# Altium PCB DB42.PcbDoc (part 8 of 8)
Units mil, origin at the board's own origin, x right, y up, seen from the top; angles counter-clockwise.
Board outline 3236.22 x 4456.69 mil, 8 copper layers (Top Layer, MidLayer1, MidLayer2, GND-Layer5, MidLayer3, VCC, MidLayer4, Bottom Layer), stack 62.194 mil thick; 214 components, 470 nets, 1802 pads, 1663 vias.
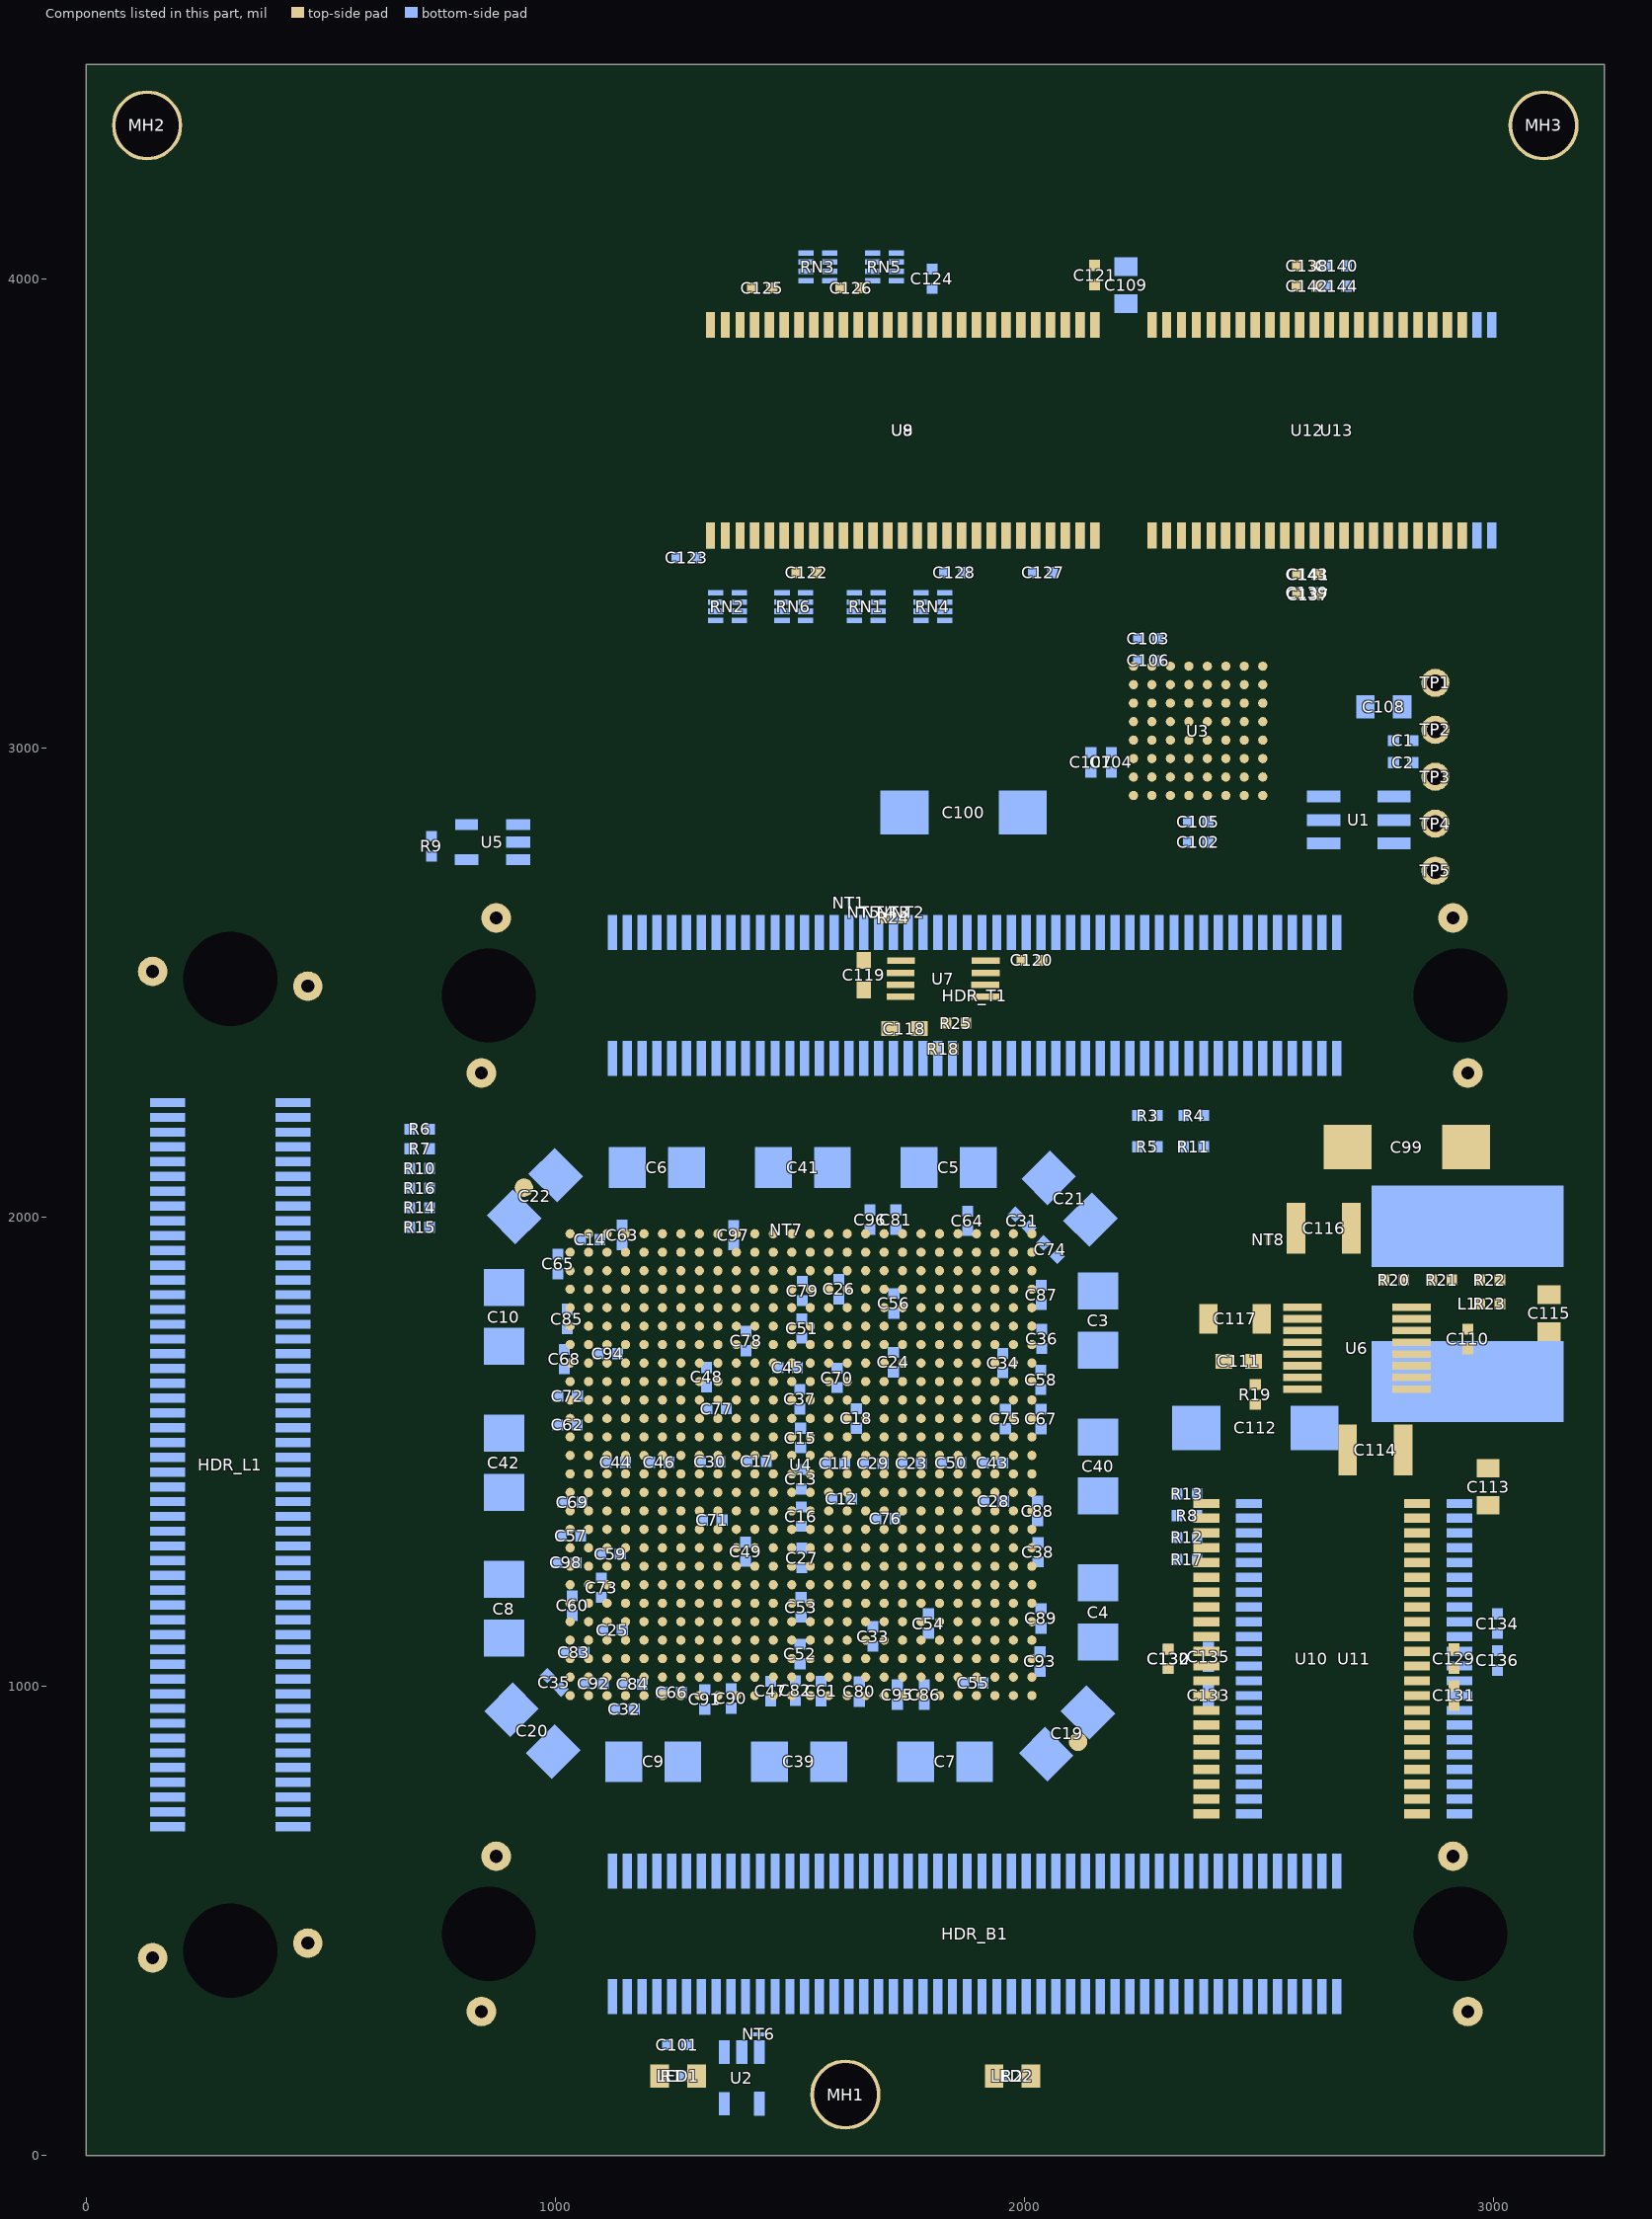
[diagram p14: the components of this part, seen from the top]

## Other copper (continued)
Bottom Layer:
  rectangle net 1V2: 2641.13,1901.74 2787.4,2043.82
  rectangle net LX: 2637.8,1618.11 2799.21,1728.35
  rectangle net 5V0: 2629.92,2248.03 2740.16,2346.46
  rectangle net 5V0: 2645.67,2248.03 2740.16,2346.46
  rectangle net 3V3: 2562.99,2570.86 2610.24,2704.72
  rectangle net 3V3: 2562.99,570.86 2610.24,704.72
  rectangle net GND: 2645.67,2598.43 2740.16,2696.85
  rectangle net 5V0: 2645.67,251.97 2740.16,346.46
  rectangle net GND: 2645.67,598.43 2740.16,696.85
GND-Layer5 (plane layer: these items are gaps in the copper):
  rectangle: 2645.67,2251.97 2740.16,2283.46
  rectangle: 2708.66,2283.47 2740.16,2346.46
  rectangle: 2570.87,2661.42 2602.36,2724.41
  rectangle: 2661.42,1641.73 2720.47,1696.85
  rectangle: 2645.67,251.97 2708.66,283.46
  rectangle: 2708.66,314.96 2740.16,346.46
  rectangle: 2570.87,661.42 2602.36,724.41
  text "GND" at 1645.67,437.01 h60
VCC (plane layer: these items are gaps in the copper):
  rectangle: 3102.36,4334.65 3228.35,4444.88
  rectangle: 23.62,4330.71 129.92,4440.94
  lines w19.68: 2624.02,0 2624.02,356.3 2787.4,519.68 2787.4,637.8 2838.58,688.98 2952.76,688.98 3055.12,791.34 3055.12,1244.09 3055.12,1287.4 3055.12,1389.76 3009.88,1435 2740,1435 2735,1440 2735,1587.6 2716.3,1606.3 2614.17,1606.3 2582.68,1574.8 2452.76,1574.8 2437.01,1590.55 2437.01,2015.75 2624.02,2202.76 2624.02,2383.86 2629.92,2389.76 2795.28,2389.76 2917.32,2267.72 3068.72,2267.72 3116,2315 3116,3975 3046,4045 2728,4045 2711.76,4061.24 2711.76,4456.69
  lines w30: 25.58,627.79 25.58,36.41 36.41,25.58 3205.87,25.58 3210.79,30.5 3210.79,4423.08 3201.94,4431.94 3124.2,4431.94 3123.22,4432.92 38.38,4432.92 27.55,4422.1 27.55,628.78
  text "5V0" at 2791.34,1826.77 h60
  text "3V3" at 1657.48,437.01 h60

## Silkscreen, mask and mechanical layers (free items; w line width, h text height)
Top Overlay:
  rectangle: 998.77,581.74 1627.79,617.74
  rectangle: 998.77,318.48 1627.79,354.48
  rectangle: 2710.5,318.48 2788.79,617.48
  region: 1073.79,617.74 998.77,617.74 998.77,318.48 1073.79,318.48
  region: 1689.96,4181.1 1689.96,4456.69 1670.28,4456.69 1670.28,4181.1
  region: 1598.43,4181.1 1598.43,4456.69 1593.51,4456.69 1593.51,4181.1
  region: 1618.11,4181.1 1618.11,4456.69 1610.24,4456.69 1610.24,4181.1
  region: 1640.75,4181.1 1640.75,4456.69 1628.94,4456.69 1628.94,4181.1
  region: 1664.37,4181.1 1664.37,4456.69 1649.61,4456.69 1649.61,4181.1
  region: 1579.72,4181.1 1579.72,4456.69 1576.77,4456.69 1576.77,4181.1
  rectangle: 1301.18,3503.94 2179.13,3596.46
  rectangle: 2238.19,3502.95 2966.89,3595.47
  region: 2787.4,695.23 2787.4,1424.21 2694.88,1424.21 2694.88,695.23
  rectangle: 1775.59,2456.69 1803,2559.05
  rectangle: 1337.26,129.92 1351.38,208.66
  rectangle: 2049.67,129.92 2063.98,208.66
  rectangle: 2736.22,1620.75 2768.58,1820.75
  region: 1840.85,253.71 1833.78,260.78 1756,183 1763.07,175.93
  rectangle: 1756,183 1766,218
  region: 1772.38,166.61 1779.46,159.54 1857.24,237.33 1850.17,244.4
  region: 1814.46,159.54 1814.46,169.54 1779.46,169.54 1779.46,159.54
  region: 3099.71,4136.09 3089.71,4136.09 3089.71,4026.09 3099.71,4026.09
  region: 3064.97,4111.34 3072.04,4104.27 3096.79,4129.02 3089.71,4136.09
  rectangle: 3112.89,4026.09 3122.89,4136.09
  region: 3122.89,4136.09 3115.82,4129.02 3140.56,4104.27 3147.64,4111.34
  region: 123.34,4136.09 113.34,4136.09 113.34,4026.09 123.34,4026.09
  region: 88.59,4111.34 95.66,4104.27 120.41,4129.02 113.34,4136.09
  rectangle: 136.51,4026.09 146.51,4136.09
  region: 146.51,4136.09 139.44,4129.02 164.19,4104.27 171.26,4111.34
  lines w3: 1118.09,192.91 1133.09,202.91 1123.09,202.91 1143.09,217.91 ; 1133.09,207.91 1143.09,217.91 ; 1133.09,212.91 1143.09,217.91 ; 2137.52,187.01 2152.52,197.01 2142.52,197.01 2162.52,212.01 ; 2152.52,202.01 2162.52,212.01 ; 2152.52,207.01 2162.52,212.01
  lines w5: 971.79,2024.27 992.13,2003.94 ; 1078.13,171.78 1103.06,171.78 ; 1103.06,173.36 1126.68,173.36 ; 1104.64,163.12 1126.68,172.05 ; 1104.64,180.97 1126.68,172.05 ; 1105.03,168.63 1126.68,172.96 ; 1105.03,175.46 1126.68,171.13 ; 1126.68,156.3 1126.68,187.79 ; 1126.68,171.78 1150.04,171.78 ; 1329.1,3386.03 1329.1,3414.79 ; 1687.62,2591.03 1707.96,2570.7 ; 2097.56,165.88 2122.48,165.88 ; 2122.48,167.45 2146.1,167.45 ; 2124.06,157.21 2146.1,166.14 ; 2124.06,175.07 2146.1,166.14 ; 2124.45,162.73 2146.1,167.06 ; 2124.45,169.56 2146.1,165.23 ; 2146.1,150.39 2146.1,181.89 ; 2146.1,165.88 2169.46,165.88 ; 2271.78,3384.98 2271.78,3413.74 ; 2646.32,3273.29 2625.98,3252.95 ; 2907.18,728.42 2878.41,728.42 ; 2908.93,1634.16 2880.16,1634.16 ; 3031.5,1822.83 3073.01,1882.13 ; 992.13,2003.94 964.13,2016.94 971.68,2024.38 979.13,2031.94 992.13,2003.94 ; 1126.68,172.05 1103.06,187.79 1103.06,156.3 1126.68,172.05 ; 1329.1,3414.79 1318.5,3385.8 1329.1,3385.88 1339.71,3385.8 1329.1,3414.79 ; 1707.96,2570.7 1694.96,2598.69 1687.52,2591.14 1679.96,2583.69 1707.96,2570.7 ; 2146.1,166.14 2122.48,150.39 2122.48,181.89 2146.1,166.14 ; 2271.78,3413.74 2282.39,3384.75 2271.78,3384.83 2261.17,3384.75 2271.78,3413.74 ; 2625.98,3252.95 2638.98,3280.95 2646.43,3273.4 2653.98,3265.95 2625.98,3252.95 ; 2878.41,728.42 2907.4,717.82 2907.33,728.42 2907.4,739.03 2878.41,728.42 ; 2880.16,1634.16 2909.15,1623.56 2909.08,1634.16 2909.15,1644.77 2880.16,1634.16
  lines w7: 971.13,2018.93 978.13,2011.94 ; 977.13,2024.94 984.13,2017.94 ; 1324.86,3389.33 1324.86,3399.23 ; 1333.35,3389.33 1333.35,3399.23 ; 1686.96,2585.69 1693.96,2578.69 ; 1692.96,2591.69 1699.96,2584.69 ; 2267.54,3388.29 2267.54,3398.18 ; 2276.02,3388.29 2276.02,3398.18 ; 2633.98,3266.95 2640.98,3273.95 ; 2639.98,3260.95 2646.98,3267.95 ; 2893.97,724.18 2903.87,724.18 ; 2893.97,732.67 2903.87,732.67 ; 2895.72,1629.92 2905.62,1629.92 ; 2895.72,1638.41 2905.62,1638.41
  lines w7.87: 1301.18,3722.33 ccw(c1301.18,3752.07) 1301.18,3781.82 ; 2179.13,3722.33 cw(c2179.13,3752.07) 2179.13,3781.82 ; 1708.66,4185.04 1708.66,4452.76 2972.66,4452.76 2972.66,4185.04 1708.66,4185.04
  text "Xilinx®  Spartan™3A-DSP" at 1708.66,4311.02 h98.43
  text "XC3SD1800A-4FGG676C" at 1708.66,4185.04 h98.43
  text "SRAM-256Kx16" at 2352.07,3683.79 h50
  text "DRAM-16Mx16" at 1482.53,3682.61 h50
  text "FLASH" at 2491.1,2767.2 h34
  text "MAX" at 1831.9,2475.9 h22 r90
  text "8860" at 1865.1,2465.2 h25 r90
  text "1831" at 2721.4,1671.7 h40 r90
  text "SRAM-256Kx16" at 2605.68,808.76 h50 r90
  text "DB42.02" at 1027.8,488.46 h98.42
  text "XC3SD1800A-4FGG676C" at 1027.8,430.47 h60
  text "Xilinx Daughter Board" at 1028.31,354.49 h60
  text "DB42.02" at 1625.79,318.46 h60
  text "PROGRAM" at 1145,60 h55.12
  text "POWER" at 1895,60 h55.12
Bottom Overlay:
  drawing of 1137 lines, arcs and shapes, not listed
  text "Xilinx®  Spartan™3A-DSP" at 2968.73,4318.9 h98.43
  text "XC3SD1800A-4FGG676C" at 2968.73,4185.04 h98.43
  text "MANUFACTURE" at 1006.78,3830.86 h40
  text "DATE" at 1007.88,3764.06 h40
  text "SRAM-256Kx16" at 2939.9,3684 h50
  text "DRAM-16Mx16" at 1997.78,3682.61 h50
  text ".Application_BuildNumber" at 627.63,3398.29 h60
  text "BUILD No:" at 901.4,3398.07 h34
  text "SVN 9250" at 627.63,3338.95 h60
  text "REVISION No:" at 976.18,3338.74 h34
  text "PCB MANUFACTURER:" at 1185.04,3279.53 h34
  text "COMPLIANCE:" at 1182.36,3081.45 h45
  text "CLASS 2" at 432.36,2991.45 h40
  text "IPC-A-600H" at 1092.36,2991.45 h40
  text "CLASS 2" at 432.36,2911.45 h40
  text "TYPE 3" at 682.36,2911.45 h40
  text "IPC-6012D" at 1092.36,2911.45 h40
  text "DS2406" at 2711.2,2774.8 h28 r270
  text "1" at 116.93,2272.44 h39.37
  text "1" at 1085.43,2256.69 h39.37
  text "SRAM-256Kx16" at 2709.68,784.5 h50 r270
  text "1" at 1073.62,264.57 h39.37
  text "DB42" at 412.16,123.67 h120
Bottom Paste:
  rectangle: 2313.39,1935.83 2443.7,2027.16
PCB Boundary:
  lines w3.94: 1523.62,4456.69 3236.22,4456.69 ; 1523.62,4456.69 3236.22,4456.69 ; 1523.62,4456.69 0,4456.69 0,0 1618.11,0 3236.22,0 3236.22,4456.69 ; 1523.62,4456.69 3236.22,4456.69 ; 1523.62,4456.69 3236.22,4456.69
Mechanical 7:
  lines w7.87: 2448.19,1719.13 2271.61,1846.46 2271.61,2043.31 2448.19,2170.63 ; 2511.22,1754.56 2334.65,1881.89 2334.65,2078.74 2511.22,2206.07 ; 2602.32,1944.88 2681.06,1944.88 ; 2641.69,1905.51 2641.69,1984.25 ; 2661.42,1980.32 2740.16,1980.32 ; 2700.79,1940.94 2700.79,2019.69 ; 2831.26,1719.13 3007.83,1846.46 3007.83,2043.31 2831.26,2170.63 ; 2894.29,1754.56 3070.87,1881.89 3070.87,2078.74 2894.29,2206.07
Keep Away From Edge:
  lines w7.87: 200,200 3030,200 3030,4250 200,4250 200,200

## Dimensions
307.09,437.01 to 858.27,472.44 on Dimensions
2929.13,472.44 to 2929.13,2472.44 on Dimensions
3106.3,4326.77 to 3236.22,0 on Dimensions
129.92,4342.52 to 0,15.75 on Dimensions
307.09,-15.75 to 0,4275.59 on Dimensions
3236.22,0 to 0,4059.06 on Dimensions
0,4456.69 to -19.69,0 on Dimensions
2929.14,472.44 to 3236.22,-3.94 on Dimensions
1618.11,153.54 to 3236.22,19.69 on Dimensions
307.09,437.01 to -19.69,0 on Dimensions
1618.11,129.92 to 3244.09,0 on Dimensions
2929.14,472.44 to 3244.09,0 on Dimensions
2865.92,4456.69 to 3106.3,4326.77 on Dimensions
